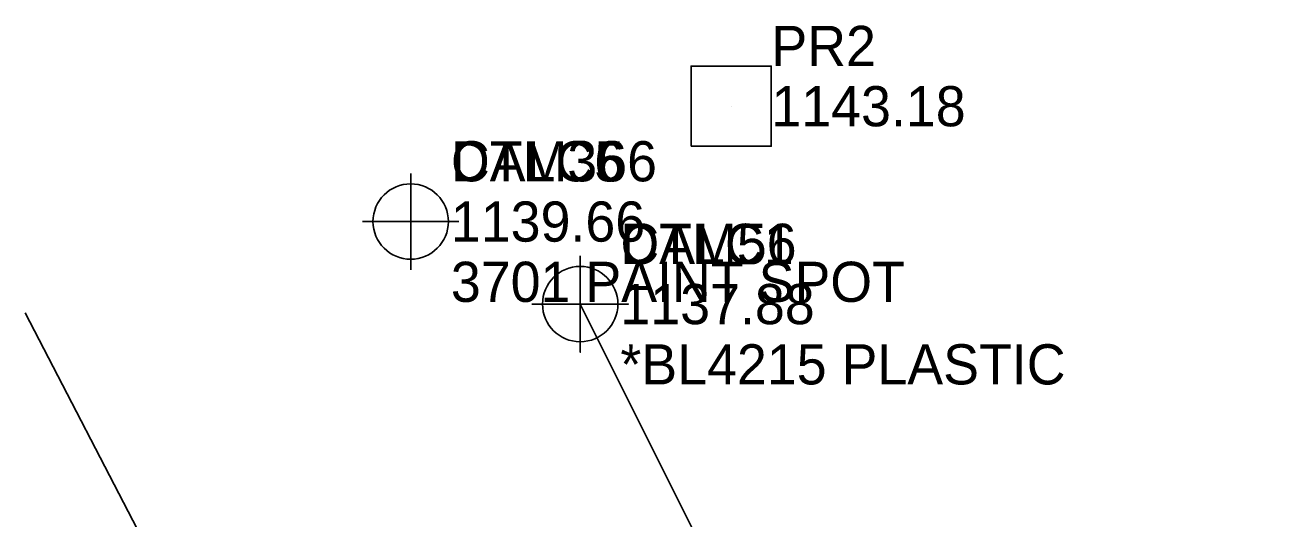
# Model space of a CAD drawing. Extents: x 1286007 to 1287145, y 857718 to 858514.
# Drawn here: x 1286687.7 to 1286766.3, y 858345.1 to 858375.8 of the extents above; entities that cross this region are included whole.
import ezdxf

# ---------------------------------------------------------------- set-up
doc = ezdxf.new("R2010")
doc.units = 0
for name, color, linetype in [('Cogo Default Point CELL', 7, 'Continuous'), ('COGO Default Point Elevation', 7, 'Continuous'), ('COGO Default Point Number', 7, 'Continuous'), ('Exist Property Iron Pin Cogo Comment', 7, 'Continuous'), ('Exist Property Iron Pin Cogo Elevation', 7, 'Continuous'), ('Exist Property Iron Pin Cogo Number', 7, 'Continuous'), ('Exist Property Monument CELL', 7, 'Continuous'), ('Exist Property Monument Cogo Elevation', 7, 'Continuous'), ('Exist Property Monument Cogo Number', 7, 'Continuous'), ('Exist Right of Way Line', 7, 'Continuous'), ('Exist Structure Minor Pipes HDPE 15 Inch', 7, 'Continuous'), ('Exist Structure Minor Pipes RCP 15 Inch Cogo Comment', 7, 'Continuous'), ('Exist Structure Minor Pipes RCP 15 Inch Cogo Elevation', 7, 'Continuous'), ('Exist Structure Minor Pipes RCP 15 Inch Cogo Number', 7, 'Continuous'), ('Exist Structure Minor Pipes RCP 15 Inch Cogo Point CELL', 7, 'Continuous')]:
    doc.layers.add(name, color=color, linetype=linetype)

msp = doc.modelspace()

# ---------------------------------------------------------------- linework, layer by layer
at = {"layer": 'Cogo Default Point CELL'}
for points in [[(1286711.654, 858366.606), (1286711.654, 858363.606)], [(1286711.654, 858366.606), (1286711.654, 858363.606)], [(1286708.654, 858363.606), (1286711.654, 858363.606)], [(1286708.654, 858363.606), (1286711.654, 858363.606)], [(1286711.654, 858363.606), (1286714.654, 858363.606)], [(1286711.654, 858363.606), (1286711.654, 858360.606)], [(1286711.654, 858363.606), (1286714.654, 858363.606)], [(1286711.654, 858363.606), (1286711.654, 858360.606)], [(1286722.196, 858361.47), (1286722.196, 858358.47)], [(1286719.196, 858358.47), (1286722.196, 858358.47)], [(1286722.196, 858358.47), (1286725.196, 858358.47)], [(1286722.196, 858358.47), (1286722.196, 858355.47)]]:
    msp.add_lwpolyline(points, dxfattribs=at)
for centre in [(1286711.654, 858363.606), (1286711.654, 858363.606), (1286722.196, 858358.47)]:
    msp.add_circle(centre, 2.344, dxfattribs=at)
at = {"layer": 'Exist Property Monument CELL'}
msp.add_line((1286731.586, 858370.784), (1286731.586, 858370.784), dxfattribs=at)
msp.add_lwpolyline([(1286729.091, 858368.289), (1286729.091, 858373.279), (1286734.081, 858373.279), (1286734.081, 858368.289), (1286729.091, 858368.289)], dxfattribs=at)
at = {"layer": 'Exist Right of Way Line'}
msp.add_line((1286723.626, 858288.506), (1286687.684, 858357.934), dxfattribs=at)
at = {"layer": 'Exist Structure Minor Pipes HDPE 15 Inch'}
msp.add_line((1286722.196, 858358.47), (1286766.264, 858270.382), dxfattribs=at)
at = {"layer": 'Exist Structure Minor Pipes RCP 15 Inch Cogo Point CELL'}
msp.add_lwpolyline([(1286722.196, 858361.47), (1286722.196, 858355.47), (1286722.196, 858358.47), (1286725.196, 858358.47), (1286719.196, 858358.47)], dxfattribs=at)
msp.add_circle((1286722.196, 858358.47), 2.344, dxfattribs=at)

# ---------------------------------------------------------------- texts
at = {"layer": 'COGO Default Point Elevation'}
for s, p in [('1139.66', (1286714.154, 858362.356)), ('1139.66', (1286714.154, 858362.356)), ('1137.88', (1286724.696, 858357.22))]:
    msp.add_text(s, height=2.5, dxfattribs=at).set_placement(p)
at = {"layer": 'COGO Default Point Number'}
for s, p in [('CALC5', (1286714.154, 858366.106)), ('CALC6', (1286714.154, 858366.106)), ('CALC1', (1286724.696, 858360.97))]:
    msp.add_text(s, height=2.5, dxfattribs=at).set_placement(p)
at = {"layer": 'Exist Property Iron Pin Cogo Comment'}
msp.add_text('3701 PAINT SPOT', height=2.5, dxfattribs=at).set_placement((1286714.154, 858358.606))
at = {"layer": 'Exist Property Iron Pin Cogo Elevation'}
msp.add_text('1139.66', height=2.5, dxfattribs=at).set_placement((1286714.154, 858362.356))
at = {"layer": 'Exist Property Iron Pin Cogo Number'}
msp.add_text('DTM366', height=2.5, dxfattribs=at).set_placement((1286714.154, 858366.106))
at = {"layer": 'Exist Property Monument Cogo Elevation'}
msp.add_text('1143.18', height=2.5, dxfattribs=at).set_placement((1286734.086, 858369.534))
at = {"layer": 'Exist Property Monument Cogo Number'}
msp.add_text('PR2', height=2.5, dxfattribs=at).set_placement((1286734.086, 858373.284))
at = {"layer": 'Exist Structure Minor Pipes RCP 15 Inch Cogo Comment'}
msp.add_text('*BL4215 PLASTIC', height=2.5, dxfattribs=at).set_placement((1286724.696, 858353.47))
at = {"layer": 'Exist Structure Minor Pipes RCP 15 Inch Cogo Elevation'}
msp.add_text('1137.88', height=2.5, dxfattribs=at).set_placement((1286724.696, 858357.22))
at = {"layer": 'Exist Structure Minor Pipes RCP 15 Inch Cogo Number'}
msp.add_text('DTM56', height=2.5, dxfattribs=at).set_placement((1286724.696, 858360.97))

doc.saveas('drawing.dxf')
